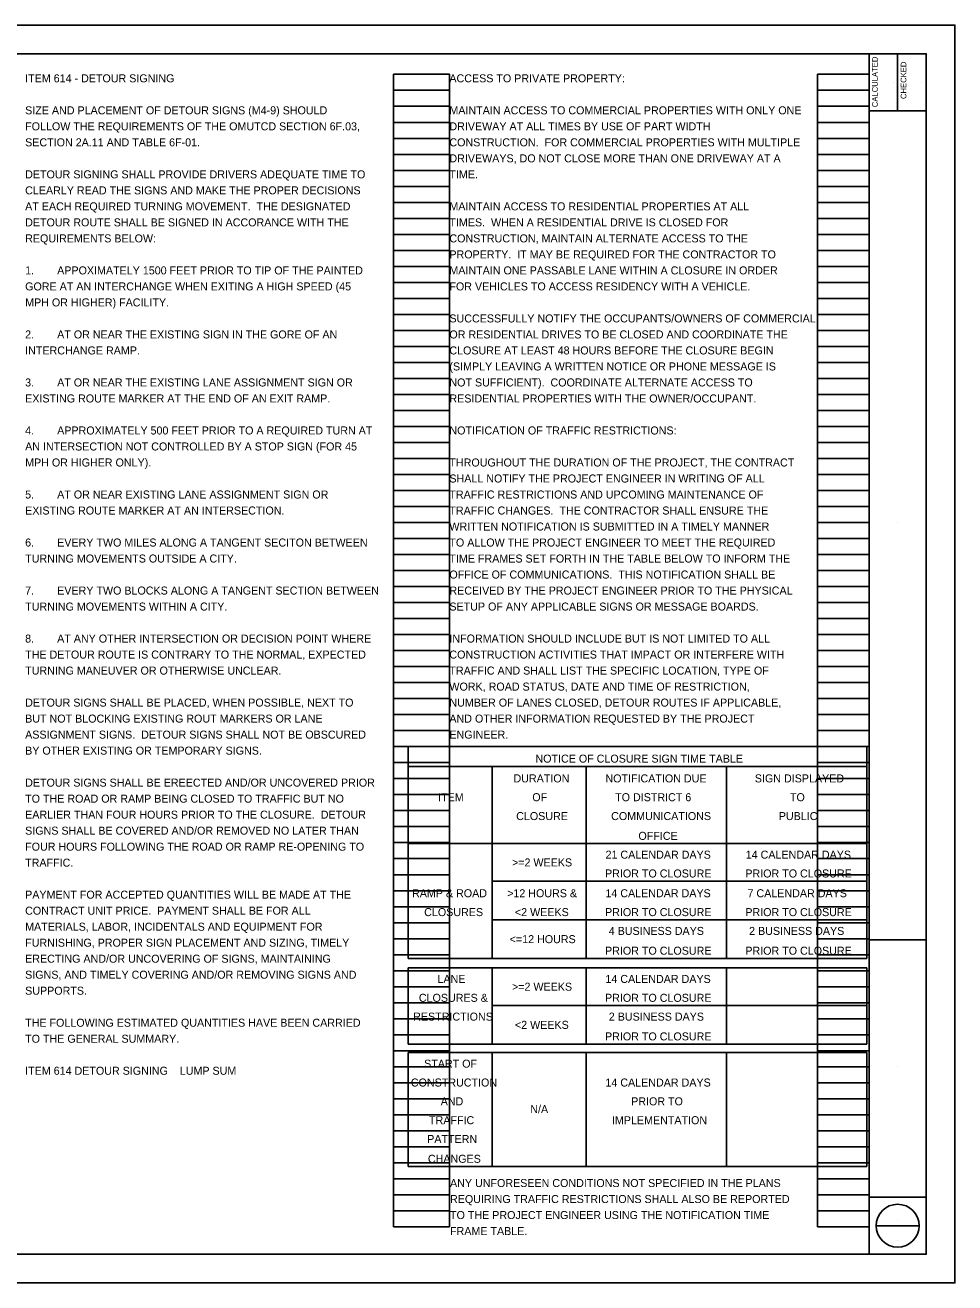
# Model space of a CAD drawing. Extents: x 0 to 34, y 0 to 22.
# Drawn here: x 17.74 to 34, y 0 to 22 of the extents above; entities that cross this region are included whole.
import ezdxf

# ---------------------------------------------------------------- set-up
doc = ezdxf.new("R2010")
doc.units = 0
for name, color, linetype in [('BD_P_Text', 7, 'Continuous'), ('SH_Border', 7, 'Continuous'), ('SH_Cut_Line', 7, 'Continuous'), ('SH_Data', 7, 'Continuous'), ('SH_Text', 7, 'Continuous')]:
    doc.layers.add(name, color=color, linetype=linetype)

msp = doc.modelspace()

# ---------------------------------------------------------------- linework, layer by layer
at = {"layer": 'SH_Border'}
for p, q in [((32.5, 0.5), (32.5, 21.5)), ((33, 21.5), (33, 20.5)), ((32.5, 20.5), (33.5, 20.5)), ((32.5, 6), (33.5, 6)), ((32.5, 1.5), (33.5, 1.5))]:
    msp.add_line(p, q, dxfattribs=at)
msp.add_lwpolyline([(2, 21.5), (33.5, 21.5), (33.5, 0.5), (2, 0.5)], close=True, dxfattribs=at)
at = {"layer": 'SH_Cut_Line'}
msp.add_lwpolyline([(0, 0), (34, 0), (34, 22), (0, 22)], close=True, dxfattribs=at)
at = {"layer": 'SH_Data'}
for p, q in [((24.18, 0.98), (24.18, 21.14)), ((24.18, 21.14), (25.16, 21.14)), ((25.16, 0.98), (25.16, 21.14)), ((31.6, 0.98), (31.6, 21.14)), ((31.6, 21.14), (32.5, 21.14)), ((32.5, 0.98), (32.5, 21.14)), ((32.92, 21.004), (32.92, 21.004)), ((33.42, 21.004), (33.42, 21.004)), ((24.18, 20.86), (25.16, 20.86)), ((31.6, 20.86), (32.5, 20.86)), ((24.18, 20.58), (25.16, 20.58)), ((31.6, 20.58), (32.5, 20.58)), ((24.18, 20.3), (25.16, 20.3)), ((31.6, 20.3), (32.5, 20.3)), ((24.18, 20.02), (25.16, 20.02)), ((31.6, 20.02), (32.5, 20.02)), ((24.18, 19.74), (25.16, 19.74)), ((31.6, 19.74), (32.5, 19.74)), ((24.18, 19.46), (25.16, 19.46)), ((31.6, 19.46), (32.5, 19.46)), ((24.18, 19.18), (25.16, 19.18)), ((31.6, 19.18), (32.5, 19.18)), ((24.18, 18.9), (25.16, 18.9)), ((31.6, 18.9), (32.5, 18.9)), ((24.18, 18.62), (25.16, 18.62)), ((31.6, 18.62), (32.5, 18.62)), ((24.18, 18.34), (25.16, 18.34)), ((31.6, 18.34), (32.5, 18.34)), ((24.18, 18.06), (25.16, 18.06)), ((31.6, 18.06), (32.5, 18.06)), ((24.18, 17.78), (25.16, 17.78)), ((31.6, 17.78), (32.5, 17.78)), ((24.18, 17.5), (25.16, 17.5)), ((31.6, 17.5), (32.5, 17.5)), ((24.18, 17.22), (25.16, 17.22)), ((31.6, 17.22), (32.5, 17.22)), ((24.18, 16.94), (25.16, 16.94)), ((31.6, 16.94), (32.5, 16.94)), ((24.18, 16.66), (25.16, 16.66)), ((31.6, 16.66), (32.5, 16.66)), ((24.18, 16.38), (25.16, 16.38)), ((31.6, 16.38), (32.5, 16.38)), ((24.18, 16.1), (25.16, 16.1)), ((31.6, 16.1), (32.5, 16.1)), ((24.18, 15.82), (25.16, 15.82)), ((31.6, 15.82), (32.5, 15.82)), ((24.18, 15.54), (25.16, 15.54)), ((31.6, 15.54), (32.5, 15.54)), ((24.18, 15.26), (25.16, 15.26)), ((31.6, 15.26), (32.5, 15.26)), ((24.18, 14.98), (25.16, 14.98)), ((31.6, 14.98), (32.5, 14.98)), ((24.18, 14.7), (25.16, 14.7)), ((31.6, 14.7), (32.5, 14.7)), ((24.18, 14.42), (25.16, 14.42)), ((31.6, 14.42), (32.5, 14.42)), ((24.18, 14.14), (25.16, 14.14)), ((31.6, 14.14), (32.5, 14.14)), ((24.18, 13.86), (25.16, 13.86)), ((31.6, 13.86), (32.5, 13.86)), ((24.18, 13.58), (25.16, 13.58)), ((31.6, 13.58), (32.5, 13.58)), ((24.18, 13.3), (25.16, 13.3)), ((31.6, 13.3), (32.5, 13.3)), ((33, 13.292), (33, 13.292)), ((24.18, 13.02), (25.16, 13.02)), ((31.6, 13.02), (32.5, 13.02)), ((24.18, 12.74), (25.16, 12.74)), ((31.6, 12.74), (32.5, 12.74)), ((24.18, 12.46), (25.16, 12.46)), ((31.6, 12.46), (32.5, 12.46)), ((24.18, 12.18), (25.16, 12.18)), ((31.6, 12.18), (32.5, 12.18)), ((24.18, 11.9), (25.16, 11.9)), ((31.6, 11.9), (32.5, 11.9)), ((24.18, 11.62), (25.16, 11.62)), ((31.6, 11.62), (32.5, 11.62)), ((24.18, 11.34), (25.16, 11.34)), ((31.6, 11.34), (32.5, 11.34)), ((24.18, 11.06), (25.16, 11.06)), ((31.6, 11.06), (32.5, 11.06)), ((24.18, 10.78), (25.16, 10.78)), ((31.6, 10.78), (32.5, 10.78)), ((24.18, 10.5), (25.16, 10.5)), ((31.6, 10.5), (32.5, 10.5)), ((24.18, 10.22), (25.16, 10.22)), ((31.6, 10.22), (32.5, 10.22)), ((24.18, 9.94), (25.16, 9.94)), ((31.6, 9.94), (32.5, 9.94)), ((24.18, 9.66), (25.16, 9.66)), ((31.6, 9.66), (32.5, 9.66)), ((24.18, 9.38), (25.16, 9.38)), ((24.441, 9.38), (32.462, 9.38)), ((24.441, 9.38), (24.441, 5.674)), ((31.6, 9.38), (32.5, 9.38)), ((32.462, 9.38), (32.462, 5.674)), ((24.18, 9.1), (25.16, 9.1)), ((24.441, 9.034), (32.462, 9.034)), ((25.907, 9.034), (25.907, 5.674)), ((27.554, 9.034), (27.554, 5.674)), ((30.008, 9.034), (30.008, 5.674)), ((31.6, 9.1), (32.5, 9.1)), ((24.18, 8.82), (25.16, 8.82)), ((31.6, 8.82), (32.5, 8.82)), ((24.18, 8.54), (25.16, 8.54)), ((31.6, 8.54), (32.5, 8.54)), ((24.18, 8.26), (25.16, 8.26)), ((31.6, 8.26), (32.5, 8.26)), ((24.18, 7.98), (25.16, 7.98)), ((31.6, 7.98), (32.5, 7.98)), ((24.18, 7.7), (25.16, 7.7)), ((24.441, 7.684), (32.462, 7.684)), ((31.6, 7.7), (32.5, 7.7)), ((24.18, 7.42), (25.16, 7.42)), ((31.6, 7.42), (32.5, 7.42)), ((24.18, 7.14), (25.16, 7.14)), ((31.6, 7.14), (32.5, 7.14)), ((24.18, 6.86), (25.16, 6.86)), ((25.907, 7.025), (32.462, 7.025)), ((31.6, 6.86), (32.5, 6.86)), ((24.18, 6.58), (25.16, 6.58)), ((31.6, 6.58), (32.5, 6.58)), ((24.18, 6.3), (25.16, 6.3)), ((25.907, 6.349), (32.462, 6.349)), ((31.6, 6.3), (32.5, 6.3)), ((24.18, 6.02), (25.16, 6.02)), ((31.6, 6.02), (32.5, 6.02)), ((24.18, 5.74), (25.16, 5.74)), ((31.6, 5.74), (32.5, 5.74)), ((24.441, 5.674), (32.462, 5.674)), ((24.441, 5.509), (32.462, 5.509)), ((24.441, 5.509), (24.441, 4.175)), ((25.907, 5.509), (25.907, 4.175)), ((27.554, 5.509), (27.554, 4.175)), ((30.008, 5.509), (30.008, 4.175)), ((32.462, 5.509), (32.462, 4.175)), ((24.18, 5.46), (25.16, 5.46)), ((31.6, 5.46), (32.5, 5.46)), ((24.18, 5.18), (25.16, 5.18)), ((31.6, 5.18), (32.5, 5.18)), ((24.18, 4.9), (25.16, 4.9)), ((25.907, 4.851), (32.462, 4.851)), ((31.6, 4.9), (32.5, 4.9)), ((24.18, 4.62), (25.16, 4.62)), ((31.6, 4.62), (32.5, 4.62)), ((24.18, 4.34), (25.16, 4.34)), ((31.6, 4.34), (32.5, 4.34)), ((24.18, 4.06), (25.16, 4.06)), ((24.441, 4.175), (32.462, 4.175)), ((24.441, 4.027), (32.462, 4.027)), ((24.441, 4.027), (24.441, 2.034)), ((25.907, 4.027), (25.907, 2.034)), ((27.554, 4.027), (27.554, 2.034)), ((30.008, 4.027), (30.008, 2.034)), ((31.6, 4.06), (32.5, 4.06)), ((32.462, 4.027), (32.462, 2.034)), ((24.18, 3.78), (25.16, 3.78)), ((31.6, 3.78), (32.5, 3.78)), ((33, 3.792), (33, 3.792)), ((24.18, 3.5), (25.16, 3.5)), ((31.6, 3.5), (32.5, 3.5)), ((24.18, 3.22), (25.16, 3.22)), ((31.6, 3.22), (32.5, 3.22)), ((24.18, 2.94), (25.16, 2.94)), ((31.6, 2.94), (32.5, 2.94)), ((24.18, 2.66), (25.16, 2.66)), ((31.6, 2.66), (32.5, 2.66)), ((24.18, 2.38), (25.16, 2.38)), ((31.6, 2.38), (32.5, 2.38)), ((24.18, 2.1), (25.16, 2.1)), ((24.441, 2.034), (32.462, 2.034)), ((31.6, 2.1), (32.5, 2.1)), ((24.18, 1.82), (25.16, 1.82)), ((31.6, 1.82), (32.5, 1.82)), ((24.18, 1.54), (25.16, 1.54)), ((31.6, 1.54), (32.5, 1.54)), ((24.18, 1.26), (25.16, 1.26)), ((31.6, 1.26), (32.5, 1.26)), ((24.18, 0.98), (25.16, 0.98)), ((31.6, 0.98), (32.5, 0.98)), ((32.625, 1), (33.375, 1)), ((33, 1.085), (33, 1.085)), ((33, 0.745), (33, 0.745))]:
    msp.add_line(p, q, dxfattribs=at)
msp.add_circle((33, 1), 0.375, dxfattribs=at)

# ---------------------------------------------------------------- texts
at = {"layer": 'BD_P_Text'}
for s, p in [('ITEM 614 - DETOUR SIGNING', (17.74, 21)), ('ACCESS TO PRIVATE PROPERTY:', (25.16, 21)), ('SIZE AND PLACEMENT OF DETOUR SIGNS (M4-9) SHOULD ', (17.74, 20.44)), ('MAINTAIN ACCESS TO COMMERCIAL PROPERTIES WITH ONLY ONE ', (25.16, 20.44)), ('FOLLOW THE REQUIREMENTS OF THE OMUTCD SECTION 6F.03, ', (17.74, 20.16)), ('DRIVEWAY AT ALL TIMES BY USE OF PART WIDTH ', (25.16, 20.16)), ('SECTION 2A.11 AND TABLE 6F-01.', (17.74, 19.88)), ('CONSTRUCTION.  FOR COMMERCIAL PROPERTIES WITH MULTIPLE ', (25.16, 19.88)), ('DRIVEWAYS, DO NOT CLOSE MORE THAN ONE DRIVEWAY AT A ', (25.16, 19.6)), ('DETOUR SIGNING SHALL PROVIDE DRIVERS ADEQUATE TIME TO ', (17.74, 19.32)), ('TIME.', (25.16, 19.32)), ('CLEARLY READ THE SIGNS AND MAKE THE PROPER DECISIONS ', (17.74, 19.04)), ('AT EACH REQUIRED TURNING MOVEMENT.  THE DESIGNATED ', (17.74, 18.76)), ('MAINTAIN ACCESS TO RESIDENTIAL PROPERTIES AT ALL ', (25.16, 18.76)), ('DETOUR ROUTE SHALL BE SIGNED IN ACCORANCE WITH THE ', (17.74, 18.48)), ('TIMES.  WHEN A RESIDENTIAL DRIVE IS CLOSED FOR ', (25.16, 18.48)), ('REQUIREMENTS BELOW:', (17.74, 18.2)), ('CONSTRUCTION, MAINTAIN ALTERNATE ACCESS TO THE ', (25.16, 18.2)), ('PROPERTY.  IT MAY BE REQUIRED FOR THE CONTRACTOR TO ', (25.16, 17.92)), ('1.', (17.74, 17.64)), ('APPOXIMATELY 1500 FEET PRIOR TO TIP OF THE PAINTED ', (18.3, 17.64)), ('MAINTAIN ONE PASSABLE LANE WITHIN A CLOSURE IN ORDER ', (25.16, 17.64)), ('GORE AT AN INTERCHANGE WHEN EXITING A HIGH SPEED (45 ', (17.74, 17.36)), ('FOR VEHICLES TO ACCESS RESIDENCY WITH A VEHICLE.', (25.16, 17.36)), ('MPH OR HIGHER) FACILITY.', (17.74, 17.08)), ('SUCCESSFULLY NOTIFY THE OCCUPANTS/OWNERS OF COMMERCIAL ', (25.16, 16.8)), ('2.', (17.74, 16.52)), ('AT OR NEAR THE EXISTING SIGN IN THE GORE OF AN ', (18.3, 16.52)), ('OR RESIDENTIAL DRIVES TO BE CLOSED AND COORDINATE THE ', (25.16, 16.52)), ('INTERCHANGE RAMP.', (17.74, 16.24)), ('CLOSURE AT LEAST 48 HOURS BEFORE THE CLOSURE BEGIN ', (25.16, 16.24)), ('(SIMPLY LEAVING A WRITTEN NOTICE OR PHONE MESSAGE IS ', (25.16, 15.96)), ('3.', (17.74, 15.68)), ('AT OR NEAR THE EXISTING LANE ASSIGNMENT SIGN OR ', (18.3, 15.68)), ('NOT SUFFICIENT).  COORDINATE ALTERNATE ACCESS TO ', (25.16, 15.68)), ('EXISTING ROUTE MARKER AT THE END OF AN EXIT RAMP.', (17.74, 15.4)), ('RESIDENTIAL PROPERTIES WITH THE OWNER/OCCUPANT.', (25.16, 15.4)), ('4.', (17.74, 14.84)), ('APPROXIMATELY 500 FEET PRIOR TO A REQUIRED TURN AT ', (18.3, 14.84)), ('NOTIFICATION OF TRAFFIC RESTRICTIONS:', (25.16, 14.84)), ('AN INTERSECTION NOT CONTROLLED BY A STOP SIGN (FOR 45 ', (17.74, 14.56)), ('MPH OR HIGHER ONLY).', (17.74, 14.28)), ('THROUGHOUT THE DURATION OF THE PROJECT, THE CONTRACT ', (25.16, 14.28)), ('SHALL NOTIFY THE PROJECT ENGINEER IN WRITING OF ALL ', (25.16, 14)), ('AT OR NEAR EXISTING LANE ASSIGNMENT SIGN OR ', (18.3, 13.72)), ('TRAFFIC RESTRICTIONS AND UPCOMING MAINTENANCE OF ', (25.16, 13.72)), ('5.', (17.74, 13.72)), ('EXISTING ROUTE MARKER AT AN INTERSECTION.', (17.74, 13.44)), ('TRAFFIC CHANGES.  THE CONTRACTOR SHALL ENSURE THE ', (25.16, 13.44)), ('WRITTEN NOTIFICATION IS SUBMITTED IN A TIMELY MANNER ', (25.16, 13.16)), ('6.', (17.74, 12.88)), ('EVERY TWO MILES ALONG A TANGENT SECITON BETWEEN ', (18.3, 12.88)), ('TO ALLOW THE PROJECT ENGINEER TO MEET THE REQUIRED ', (25.16, 12.88)), ('TURNING MOVEMENTS OUTSIDE A CITY.', (17.74, 12.6)), ('TIME FRAMES SET FORTH IN THE TABLE BELOW TO INFORM THE ', (25.16, 12.6)), ('OFFICE OF COMMUNICATIONS.  THIS NOTIFICATION SHALL BE ', (25.16, 12.32)), ('7.', (17.74, 12.04)), ('EVERY TWO BLOCKS ALONG A TANGENT SECTION BETWEEN ', (18.3, 12.04)), ('RECEIVED BY THE PROJECT ENGINEER PRIOR TO THE PHYSICAL ', (25.16, 12.04)), ('TURNING MOVEMENTS WITHIN A CITY.', (17.74, 11.76)), ('SETUP OF ANY APPLICABLE SIGNS OR MESSAGE BOARDS.', (25.16, 11.76)), ('8.', (17.74, 11.2)), ('AT ANY OTHER INTERSECTION OR DECISION POINT WHERE ', (18.3, 11.2)), ('INFORMATION SHOULD INCLUDE BUT IS NOT LIMITED TO ALL ', (25.16, 11.2)), ('THE DETOUR ROUTE IS CONTRARY TO THE NORMAL, EXPECTED ', (17.74, 10.92)), ('CONSTRUCTION ACTIVITIES THAT IMPACT OR INTERFERE WITH ', (25.16, 10.92)), ('TURNING MANEUVER OR OTHERWISE UNCLEAR.', (17.74, 10.64)), ('TRAFFIC AND SHALL LIST THE SPECIFIC LOCATION, TYPE OF ', (25.16, 10.64)), ('WORK, ROAD STATUS, DATE AND TIME OF RESTRICTION, ', (25.16, 10.36)), ('DETOUR SIGNS SHALL BE PLACED, WHEN POSSIBLE, NEXT TO ', (17.74, 10.08)), ('NUMBER OF LANES CLOSED, DETOUR ROUTES IF APPLICABLE, ', (25.16, 10.08)), ('BUT NOT BLOCKING EXISTING ROUT MARKERS OR LANE ', (17.74, 9.8)), ('AND OTHER INFORMATION REQUESTED BY THE PROJECT ', (25.16, 9.8)), ('ASSIGNMENT SIGNS.  DETOUR SIGNS SHALL NOT BE OBSCURED ', (17.74, 9.52)), ('ENGINEER.', (25.16, 9.52)), ('BY OTHER EXISTING OR TEMPORARY SIGNS.', (17.74, 9.24)), ('DETOUR SIGNS SHALL BE EREECTED AND/OR UNCOVERED PRIOR ', (17.74, 8.68)), ('TO THE ROAD OR RAMP BEING CLOSED TO TRAFFIC BUT NO ', (17.74, 8.4)), ('EARLIER THAN FOUR HOURS PRIOR TO THE CLOSURE.  DETOUR ', (17.74, 8.12)), ('SIGNS SHALL BE COVERED AND/OR REMOVED NO LATER THAN ', (17.74, 7.84)), ('FOUR HOURS FOLLOWING THE ROAD OR RAMP RE-OPENING TO ', (17.74, 7.56)), ('TRAFFIC.', (17.74, 7.28)), ('PAYMENT FOR ACCEPTED QUANTITIES WILL BE MADE AT THE ', (17.74, 6.72)), ('CONTRACT UNIT PRICE.  PAYMENT SHALL BE FOR ALL ', (17.74, 6.44)), ('MATERIALS, LABOR, INCIDENTALS AND EQUIPMENT FOR ', (17.74, 6.16)), ('FURNISHING, PROPER SIGN PLACEMENT AND SIZING, TIMELY ', (17.74, 5.88)), ('ERECTING AND/OR UNCOVERING OF SIGNS, MAINTAINING ', (17.74, 5.6)), ('SIGNS, AND TIMELY COVERING AND/OR REMOVING SIGNS AND ', (17.74, 5.32)), ('SUPPORTS.', (17.74, 5.04)), ('THE FOLLOWING ESTIMATED QUANTITIES HAVE BEEN CARRIED ', (17.74, 4.48)), ('TO THE GENERAL SUMMARY.', (17.74, 4.2)), ('ITEM 614 DETOUR SIGNING    LUMP SUM', (17.74, 3.64)), ('ANY UNFORESEEN CONDITIONS NOT SPECIFIED IN THE PLANS ', (25.171, 1.676)), ('REQUIRING TRAFFIC RESTRICTIONS SHALL ALSO BE REPORTED ', (25.171, 1.396)), ('TO THE PROJECT ENGINEER USING THE NOTIFICATION TIME ', (25.171, 1.116)), ('FRAME TABLE.', (25.171, 0.836))]:
    msp.add_text(s, height=0.14, dxfattribs=at).set_placement(p)
at = {"layer": 'SH_Data'}
for s, p in [('CALCULATED', (32.652, 20.565)), ('CHECKED', (33.152, 20.708))]:
    msp.add_text(s, height=0.1, rotation=90, dxfattribs=at).set_placement(p)
at = {"layer": 'SH_Text'}
for s, p in [('NOTICE OF CLOSURE SIGN TIME TABLE', (26.665, 9.1)), ('DURATION', (26.281, 8.754)), ('NOTIFICATION DUE ', (27.889, 8.754)), ('SIGN DISPLAYED', (30.502, 8.754)), ('ITEM', (24.963, 8.425)), ('OF', (26.61, 8.425)), ('TO DISTRICT 6 ', (28.059, 8.425)), ('TO', (31.116, 8.425)), ('CLOSURE', (26.328, 8.095)), ('COMMUNICATIONS', (27.989, 8.095)), ('PUBLIC', (30.921, 8.095)), (' OFFICE', (28.414, 7.749)), ('21 CALENDAR DAYS ', (27.891, 7.42)), ('14 CALENDAR DAYS ', (30.343, 7.42)), ('>=2 WEEKS', (26.255, 7.284)), ('PRIOR TO CLOSURE', (27.882, 7.091)), ('PRIOR TO CLOSURE', (30.336, 7.091)), ('RAMP & ROAD ', (24.507, 6.745)), ('>12 HOURS &', (26.17, 6.745)), ('14 CALENDAR DAYS ', (27.889, 6.745)), ('7 CALENDAR DAYS ', (30.374, 6.745)), ('CLOSURES', (24.719, 6.415)), ('<2 WEEKS', (26.306, 6.415)), ('PRIOR TO CLOSURE', (27.882, 6.415)), ('PRIOR TO CLOSURE', (30.336, 6.415)), ('4 BUSINESS DAYS ', (27.947, 6.086)), ('2 BUSINESS DAYS ', (30.402, 6.086)), ('<=12 HOURS', (26.214, 5.942)), ('PRIOR TO CLOSURE', (27.882, 5.74)), ('PRIOR TO CLOSURE', (30.336, 5.74)), ('LANE', (24.952, 5.246)), ('14 CALENDAR DAYS ', (27.889, 5.246)), ('>=2 WEEKS', (26.255, 5.11)), ('CLOSURES &', (24.626, 4.916)), ('PRIOR TO CLOSURE', (27.882, 4.916)), ('RESTRICTIONS', (24.526, 4.587)), ('2 BUSINESS DAYS ', (27.948, 4.587)), ('<2 WEEKS', (26.306, 4.443)), ('PRIOR TO CLOSURE', (27.882, 4.241)), ('START OF', (24.718, 3.764)), ('CONSTRUCTION', (24.486, 3.434)), ('14 CALENDAR DAYS ', (27.889, 3.434)), ('AND', (25.008, 3.105)), ('N/A', (26.575, 2.969)), ('PRIOR TO', (28.339, 3.105)), ('TRAFFIC', (24.804, 2.775)), ('IMPLEMENTATION', (28.003, 2.775)), ('PATTERN', (24.772, 2.446)), ('CHANGES', (24.784, 2.1))]:
    msp.add_text(s, height=0.14, dxfattribs=at).set_placement(p)

doc.saveas('drawing.dxf')
